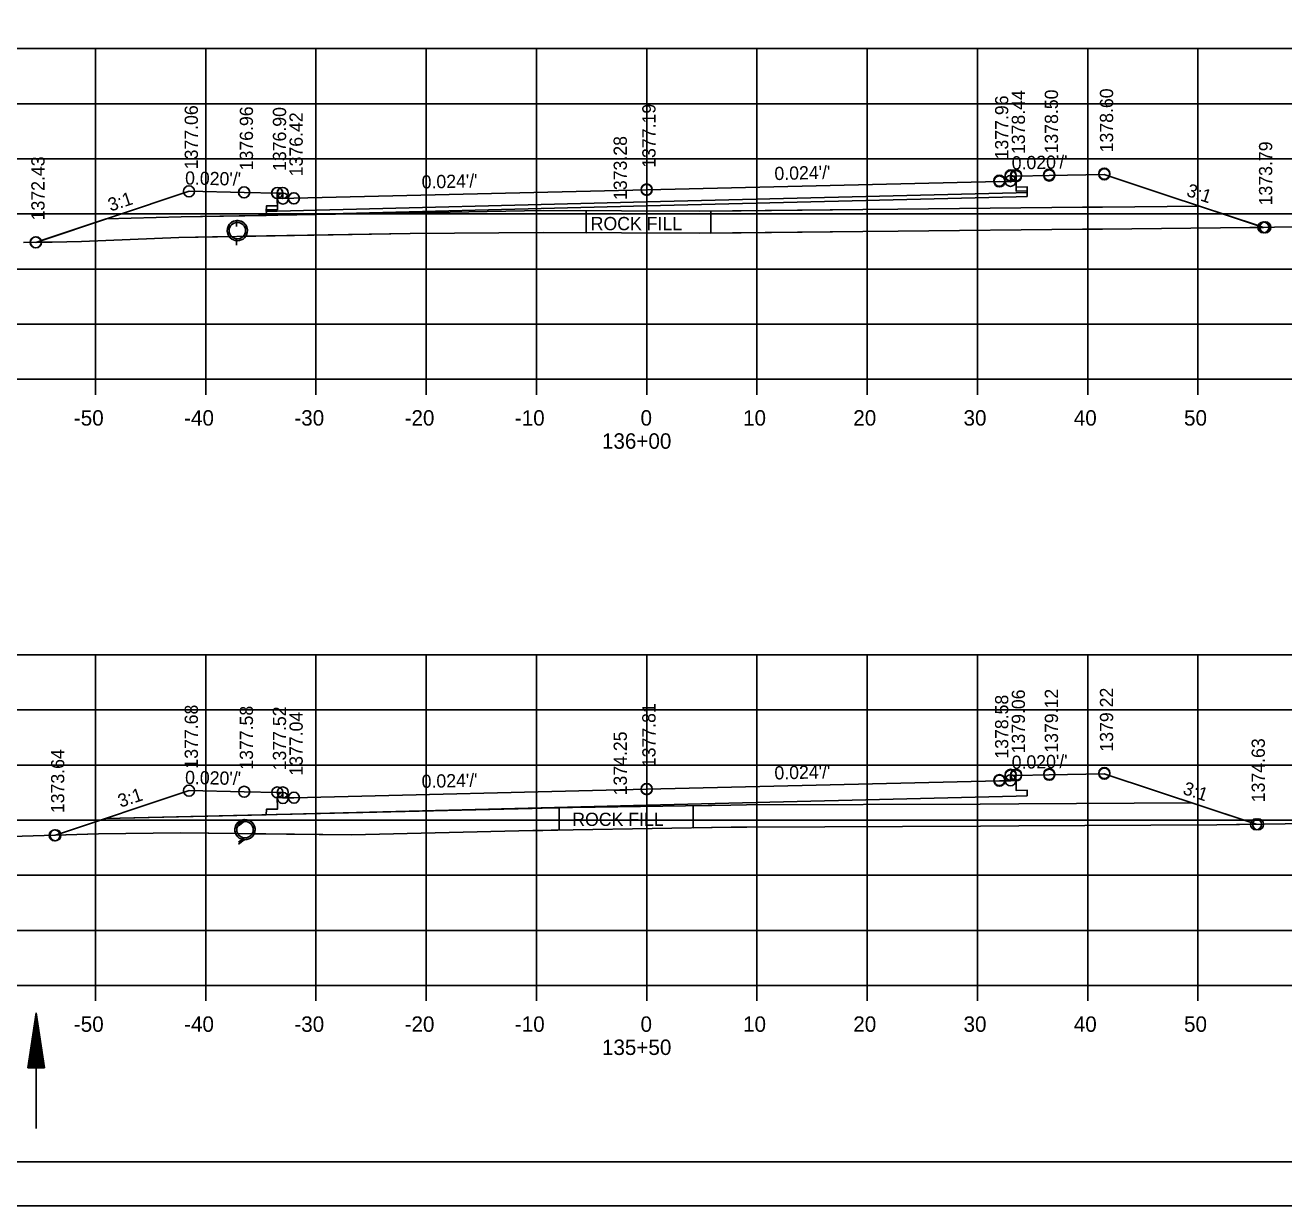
# Model space of a CAD drawing. Extents: x 1374311 to 1383814, y 384102 to 406278.
# Drawn here: x 1381572.3 to 1381686.5, y 388164.7 to 388271.8 of the extents above; entities that cross this region are included whole.
import ezdxf

# ---------------------------------------------------------------- set-up
doc = ezdxf.new("R2010")
doc.units = 0
for name, color, linetype in [('R_Axis', 7, 'Continuous'), ('R_Axis Annot', 7, 'Continuous'), ('R_Border', 7, 'Continuous'), ('R_Draft', 7, 'Continuous'), ('R_Exist Surface', 7, 'Continuous'), ('R_Fin Surface', 7, 'Continuous'), ('R_Grid', 7, 'Continuous'), ('R_No Plot', 7, 'Continuous'), ('R_Water', 7, 'Continuous'), ('R_Xsect Elev', 7, 'Continuous'), ('R_Xsect Slope', 7, 'Continuous')]:
    doc.layers.add(name, color=color, linetype=linetype)

msp = doc.modelspace()

# ---------------------------------------------------------------- linework, layer by layer
at = {"layer": 'R_Axis'}
for p, q in [((1381488.66, 388239.67), (1381768.66, 388239.67)), ((1381578.66, 388238.27), (1381578.66, 388239.67)), ((1381588.66, 388238.27), (1381588.66, 388239.67)), ((1381598.66, 388238.27), (1381598.66, 388239.67)), ((1381608.66, 388238.27), (1381608.66, 388239.67)), ((1381618.66, 388238.27), (1381618.66, 388239.67)), ((1381628.66, 388238.27), (1381628.66, 388239.67)), ((1381638.66, 388238.27), (1381638.66, 388239.67)), ((1381648.66, 388238.27), (1381648.66, 388239.67)), ((1381658.66, 388238.27), (1381658.66, 388239.67)), ((1381668.66, 388238.27), (1381668.66, 388239.67)), ((1381678.66, 388238.27), (1381678.66, 388239.67)), ((1381488.66, 388184.67), (1381768.66, 388184.67)), ((1381578.66, 388183.27), (1381578.66, 388184.67)), ((1381588.66, 388183.27), (1381588.66, 388184.67)), ((1381598.66, 388183.27), (1381598.66, 388184.67)), ((1381608.66, 388183.27), (1381608.66, 388184.67)), ((1381618.66, 388183.27), (1381618.66, 388184.67)), ((1381628.66, 388183.27), (1381628.66, 388184.67)), ((1381638.66, 388183.27), (1381638.66, 388184.67)), ((1381648.66, 388183.27), (1381648.66, 388184.67)), ((1381658.66, 388183.27), (1381658.66, 388184.67)), ((1381668.66, 388183.27), (1381668.66, 388184.67)), ((1381678.66, 388183.27), (1381678.66, 388184.67))]:
    msp.add_line(p, q, dxfattribs=at)
at = {"layer": 'R_Border'}
msp.add_line((1381786.84, 388168.67), (1381470.66, 388168.67), dxfattribs=at)
at = {"layer": 'R_Draft'}
for p, q in [((1381572.54, 388177.19), (1381573.29, 388182.19)), ((1381572.67, 388177.19), (1381573.29, 388181.36)), ((1381574.04, 388177.19), (1381573.29, 388182.19)), ((1381573.92, 388177.19), (1381573.29, 388181.36)), ((1381572.79, 388177.19), (1381573.29, 388180.5)), ((1381573.79, 388177.19), (1381573.29, 388180.5)), ((1381572.92, 388177.19), (1381573.29, 388179.67)), ((1381573.66, 388177.19), (1381573.29, 388179.67)), ((1381573.05, 388177.19), (1381573.29, 388178.82)), ((1381573.17, 388177.19), (1381573.29, 388177.98)), ((1381573.53, 388177.19), (1381573.29, 388178.82)), ((1381573.41, 388177.19), (1381573.29, 388177.98)), ((1381574.04, 388177.19), (1381572.54, 388177.19))]:
    msp.add_line(p, q, dxfattribs=at)
at = {"layer": 'R_Exist Surface'}
for p, q in [((1381591.46, 388254.07), (1381591.46, 388253.68)), ((1381591.46, 388252.24), (1381591.46, 388251.85)), ((1381592.15, 388199.72), (1381591.63, 388199.33)), ((1381592.15, 388197.89), (1381591.63, 388197.5))]:
    msp.add_line(p, q, dxfattribs=at)
for points in [[(1381572.13, 388252.07), (1381574.74, 388252.12), (1381577.38, 388252.16), (1381586.23, 388252.54), (1381607.22, 388252.89), (1381619.28, 388252.98), (1381633.47, 388252.93), (1381648.28, 388253.08), (1381651.47, 388253.12), (1381668.2, 388253.29), (1381670.01, 388253.3), (1381683.37, 388253.44), (1381687.83, 388253.5), (1381688.15, 388253.5), (1381708.29, 388253.81), (1381710.19, 388253.82), (1381728.11, 388254.09), (1381731.48, 388254.11), (1381747.31, 388254.33), (1381752.06, 388254.37), (1381757.72, 388254.57), (1381768.66, 388254.74)], [(1381561.13, 388197.89), (1381578.95, 388198.43), (1381586.36, 388198.52), (1381601.87, 388198.35), (1381618.32, 388198.73), (1381618.84, 388198.74), (1381619.23, 388198.75), (1381621.98, 388198.81), (1381636.31, 388199.03), (1381637.73, 388199.05), (1381658.93, 388199.13), (1381662.43, 388199.17), (1381680.38, 388199.25), (1381686.58, 388199.33), (1381702.39, 388199.6), (1381710.92, 388199.71), (1381721.8, 388199.86), (1381733.98, 388200.06), (1381747.51, 388200.24), (1381752.11, 388200.35), (1381756.03, 388200.45), (1381768.66, 388200.86)]]:
    msp.add_lwpolyline(points, dxfattribs=at)
for centre in [(1381591.53, 388253.16), (1381592.22, 388198.81)]:
    msp.add_circle(centre, 0.917, dxfattribs=at)
at = {"layer": 'R_Fin Surface'}
for p, q in [((1381623.17, 388252.97), (1381623.17, 388254.97)), ((1381623.17, 388252.97), (1381623.17, 388254.97)), ((1381634.49, 388252.94), (1381634.49, 388254.94)), ((1381634.49, 388254.94), (1381634.49, 388252.94)), ((1381684.12, 388253.61), (1381678.79, 388255.39)), ((1381579.63, 388254.22), (1381573.73, 388252.26)), ((1381591.46, 388254.07), (1381591.46, 388254.07)), ((1381648.28, 388253.08), (1381651.47, 388253.12)), ((1381651.47, 388253.12), (1381668.2, 388253.29)), ((1381668.2, 388253.29), (1381670.01, 388253.3)), ((1381670.01, 388253.3), (1381683.37, 388253.44)), ((1381683.37, 388253.44), (1381684.1, 388253.45)), ((1381573.76, 388252.1), (1381574.74, 388252.12)), ((1381574.74, 388252.12), (1381577.38, 388252.16)), ((1381592.29, 388252.65), (1381607.22, 388252.89)), ((1381607.22, 388252.89), (1381619.28, 388252.98)), ((1381619.28, 388252.98), (1381623.17, 388252.97)), ((1381634.49, 388252.94), (1381648.28, 388253.08)), ((1381620.73, 388200.79), (1381620.73, 388198.79)), ((1381620.73, 388198.79), (1381620.73, 388200.79)), ((1381632.87, 388200.98), (1381632.87, 388198.98)), ((1381632.87, 388200.98), (1381632.87, 388198.98)), ((1381683.93, 388199.3), (1381678.11, 388201.24)), ((1381579.58, 388199.83), (1381575.03, 388198.31)), ((1381594.15, 388200.17), (1381579.58, 388199.83)), ((1381592.14, 388199.72), (1381592.15, 388199.72)), ((1381632.87, 388198.98), (1381636.31, 388199.03))]:
    msp.add_line(p, q, dxfattribs=at)
for points in [[(1381573.24, 388252.09), (1381587.15, 388256.73), (1381592.15, 388256.63), (1381595.15, 388256.57), (1381595.65, 388256.57), (1381595.66, 388256.07), (1381596.66, 388256.09), (1381628.66, 388256.86), (1381660.66, 388257.62), (1381661.66, 388257.6), (1381661.67, 388258.1), (1381662.17, 388258.1), (1381665.17, 388258.16), (1381670.17, 388258.26), (1381684.6, 388253.45)], [(1381662.17, 388257.81), (1381662.18, 388256.73), (1381663.18, 388256.77), (1381663.17, 388256.27), (1381662.17, 388256.24), (1381628.66, 388255.4), (1381595.15, 388254.57), (1381594.15, 388254.54), (1381594.16, 388255.04), (1381595.16, 388255.05), (1381595.15, 388256.21)], [(1381579.63, 388254.22), (1381586.42, 388254.41), (1381607.45, 388254.76), (1381619.28, 388254.98), (1381633.47, 388254.93), (1381648.26, 388255.08), (1381651.44, 388255.12), (1381668.19, 388255.29), (1381670, 388255.3), (1381678.79, 388255.39)], [(1381623.17, 388254.97), (1381619.28, 388254.98), (1381607.45, 388254.76), (1381595.15, 388254.56), (1381594.15, 388254.54), (1381586.42, 388254.41), (1381579.63, 388254.22)], [(1381678.79, 388255.39), (1381670, 388255.3), (1381668.19, 388255.29), (1381651.44, 388255.12), (1381648.26, 388255.08), (1381634.49, 388254.94)], [(1381579.63, 388254.22), (1381579.63, 388254.22)], [(1381591.46, 388254.07), (1381591.46, 388254.07)], [(1381577.38, 388252.16), (1381586.23, 388252.54), (1381590.78, 388252.62)], [(1381575.03, 388198.31), (1381587.15, 388202.35), (1381592.15, 388202.25), (1381595.15, 388202.19), (1381595.65, 388202.19), (1381595.66, 388201.69), (1381596.66, 388201.71), (1381628.66, 388202.48), (1381660.66, 388203.25), (1381661.66, 388203.23), (1381661.67, 388203.73), (1381662.17, 388203.73), (1381665.17, 388203.79), (1381670.17, 388203.89), (1381683.93, 388199.3)], [(1381662.17, 388203.43), (1381662.18, 388202.35), (1381663.18, 388202.39), (1381663.17, 388201.89), (1381662.17, 388201.86), (1381628.66, 388201.03), (1381595.15, 388200.19), (1381594.15, 388200.16), (1381594.16, 388200.66), (1381595.16, 388200.67), (1381595.15, 388201.83)], [(1381579.58, 388199.83), (1381618.28, 388200.73), (1381619.19, 388200.75), (1381621.94, 388200.81), (1381636.28, 388201.03), (1381637.71, 388201.05), (1381658.92, 388201.13), (1381662.42, 388201.17), (1381678.11, 388201.24)], [(1381620.73, 388200.79), (1381619.19, 388200.75), (1381618.28, 388200.73), (1381596.51, 388200.22)], [(1381678.11, 388201.24), (1381662.42, 388201.17), (1381658.92, 388201.13), (1381637.71, 388201.05), (1381636.28, 388201.03), (1381632.87, 388200.98)], [(1381592.15, 388199.72), (1381592.15, 388199.72)], [(1381596.51, 388200.22), (1381595.15, 388200.19), (1381594.15, 388200.16)], [(1381594.15, 388200.16), (1381594.15, 388200.17)], [(1381575.03, 388198.31), (1381578.95, 388198.43), (1381586.36, 388198.52), (1381591.37, 388198.46)], [(1381593.06, 388198.44), (1381601.87, 388198.35), (1381618.32, 388198.73), (1381618.84, 388198.74), (1381619.23, 388198.75), (1381620.73, 388198.79)], [(1381620.73, 388198.79), (1381620.73, 388198.79)], [(1381636.31, 388199.03), (1381637.73, 388199.05), (1381658.93, 388199.13), (1381662.43, 388199.17), (1381680.38, 388199.25), (1381683.93, 388199.3)], [(1381683.93, 388199.3), (1381683.93, 388199.3)], [(1381575.03, 388198.31), (1381575.03, 388198.31)]]:
    msp.add_lwpolyline(points, dxfattribs=at)
for centre, radius, start, end in [((1381591.53, 388253.16), 0.917, 94.3218, 215.6764), ((1381591.53, 388253.16), 0.917, 326.2354, 94.3096), ((1381684.6, 388253.45), 0.5, 161.5651, 180.7702), ((1381573.26, 388252.1), 0.5, 0.1362, 18.2039), ((1381592.22, 388198.81), 0.917, 94.5632, 202.0149), ((1381592.22, 388198.81), 0.917, 336.7174, 94.3096)]:
    msp.add_arc(centre, radius, start, end, dxfattribs=at)
at = {"layer": 'R_Grid'}
for p, q in [((1381488.66, 388269.67), (1381768.66, 388269.67)), ((1381578.66, 388239.67), (1381578.66, 388269.67)), ((1381588.66, 388239.67), (1381588.66, 388269.67)), ((1381598.66, 388239.67), (1381598.66, 388269.67)), ((1381608.66, 388239.67), (1381608.66, 388269.67)), ((1381618.66, 388239.67), (1381618.66, 388269.67)), ((1381628.66, 388239.67), (1381628.66, 388269.67)), ((1381638.66, 388239.67), (1381638.66, 388269.67)), ((1381648.66, 388239.67), (1381648.66, 388269.67)), ((1381658.66, 388239.67), (1381658.66, 388269.67)), ((1381668.66, 388239.67), (1381668.66, 388269.67)), ((1381678.66, 388239.67), (1381678.66, 388269.67)), ((1381488.66, 388264.67), (1381768.66, 388264.67)), ((1381488.66, 388259.67), (1381768.66, 388259.67)), ((1381488.66, 388254.67), (1381768.66, 388254.67)), ((1381488.66, 388249.67), (1381768.66, 388249.67)), ((1381488.66, 388244.67), (1381768.66, 388244.67)), ((1381488.66, 388239.67), (1381768.66, 388239.67)), ((1381488.66, 388214.67), (1381768.66, 388214.67)), ((1381578.66, 388184.67), (1381578.66, 388214.67)), ((1381588.66, 388184.67), (1381588.66, 388214.67)), ((1381598.66, 388184.67), (1381598.66, 388214.67)), ((1381608.66, 388184.67), (1381608.66, 388214.67)), ((1381618.66, 388184.67), (1381618.66, 388214.67)), ((1381628.66, 388184.67), (1381628.66, 388214.67)), ((1381638.66, 388184.67), (1381638.66, 388214.67)), ((1381648.66, 388184.67), (1381648.66, 388214.67)), ((1381658.66, 388184.67), (1381658.66, 388214.67)), ((1381668.66, 388184.67), (1381668.66, 388214.67)), ((1381678.66, 388184.67), (1381678.66, 388214.67)), ((1381488.66, 388209.67), (1381768.66, 388209.67)), ((1381488.66, 388204.67), (1381768.66, 388204.67)), ((1381488.66, 388199.67), (1381768.66, 388199.67)), ((1381488.66, 388194.67), (1381768.66, 388194.67)), ((1381488.66, 388189.67), (1381768.66, 388189.67)), ((1381488.66, 388184.67), (1381768.66, 388184.67))]:
    msp.add_line(p, q, dxfattribs=at)
at = {"layer": 'R_No Plot'}
msp.add_line((1381458.26, 388164.69), (1381791.59, 388164.69), dxfattribs=at)
for points in [[(1381458.25, 388378.02), (1381791.59, 388378.02), (1381791.59, 388164.68), (1381458.25, 388164.68)], [(1381704.58, 388374.13), (1381704.58, 388364.25), (1381740.31, 388364.25), (1381740.31, 388361.33), (1381763.51, 388361.33), (1381763.51, 388338.11), (1381786.84, 388338.11), (1381786.84, 388168.67), (1381470.66, 388168.67), (1381470.66, 388374.13)], [(1381573.24, 388252.09), (1381574.74, 388252.12), (1381577.38, 388252.16), (1381586.23, 388252.54), (1381607.22, 388252.89), (1381619.28, 388252.98), (1381633.47, 388252.93), (1381648.28, 388253.08), (1381651.47, 388253.12), (1381668.2, 388253.29), (1381670.01, 388253.3), (1381683.37, 388253.44), (1381684.6, 388253.45), (1381670.17, 388258.26), (1381665.17, 388258.16), (1381662.17, 388258.1), (1381662.18, 388257.09), (1381663.18, 388257.13), (1381663.17, 388256.63), (1381662.17, 388256.6), (1381628.66, 388255.76), (1381595.15, 388254.93), (1381594.15, 388254.9), (1381594.16, 388255.4), (1381595.16, 388255.41), (1381595.15, 388256.57), (1381592.15, 388256.63), (1381587.15, 388256.73)]]:
    msp.add_lwpolyline(points, close=True, dxfattribs=at)
for centre in [(1381670.16, 388258.33), (1381670.17, 388258.33), (1381660.65, 388257.69), (1381660.66, 388257.69), (1381660.66, 388257.62), (1381661.66, 388257.67), (1381661.67, 388258.17), (1381661.67, 388258.1), (1381662.16, 388258.17), (1381662.17, 388258.17), (1381662.17, 388258.1), (1381665.16, 388258.23), (1381665.17, 388258.23), (1381665.17, 388258.16), (1381670.17, 388258.26), (1381587.14, 388256.73), (1381587.15, 388256.73), (1381587.15, 388256.73), (1381592.14, 388256.63), (1381592.15, 388256.63), (1381592.15, 388256.63), (1381595.14, 388256.57), (1381595.15, 388256.57), (1381595.15, 388256.57), (1381595.64, 388256.57), (1381595.65, 388256.57), (1381595.65, 388256.57), (1381595.66, 388256.07), (1381596.65, 388256.09), (1381596.66, 388256.09), (1381596.66, 388256.09), (1381628.65, 388256.89), (1381628.66, 388256.89), (1381628.66, 388256.86), (1381684.6, 388253.45), (1381684.73, 388253.47), (1381684.78, 388253.46), (1381573.24, 388252.09), (1381573.24, 388252.09), (1381573.24, 388252.09), (1381573.24, 388252.09), (1381573.26, 388252.1), (1381573.26, 388252.1), (1381661.67, 388203.79), (1381661.67, 388203.79), (1381661.67, 388203.73), (1381662.17, 388203.79), (1381662.17, 388203.79), (1381662.17, 388203.73), (1381665.17, 388203.85), (1381665.17, 388203.85), (1381665.17, 388203.79), (1381670.17, 388203.95), (1381670.17, 388203.95), (1381670.17, 388203.89), (1381628.66, 388202.51), (1381628.66, 388202.51), (1381628.66, 388202.48), (1381660.66, 388203.31), (1381660.66, 388203.31), (1381660.66, 388203.25), (1381661.66, 388203.29), (1381587.15, 388202.35), (1381587.15, 388202.35), (1381587.15, 388202.35), (1381592.15, 388202.25), (1381592.15, 388202.25), (1381592.15, 388202.25), (1381595.15, 388202.19), (1381595.15, 388202.19), (1381595.15, 388202.19), (1381595.65, 388202.19), (1381595.65, 388202.19), (1381595.65, 388202.19), (1381595.66, 388201.69), (1381596.66, 388201.71), (1381596.66, 388201.71), (1381596.66, 388201.71), (1381683.93, 388199.3), (1381684.12, 388199.3), (1381684.12, 388199.3), (1381574.95, 388198.29), (1381574.95, 388198.29), (1381575.02, 388198.31), (1381575.02, 388198.31), (1381575.03, 388198.31), (1381575.03, 388198.31)]:
    msp.add_circle(centre, 0.5, dxfattribs=at)
at = {"layer": 'R_Water'}
for p, q in [((1381591.46, 388253.91), (1381591.46, 388253.52)), ((1381591.46, 388252.41), (1381591.46, 388252.02)), ((1381592.15, 388199.56), (1381591.63, 388199.17)), ((1381592.15, 388198.06), (1381591.63, 388197.67)), ((1381573.29, 388171.69), (1381573.29, 388182.19))]:
    msp.add_line(p, q, dxfattribs=at)
for centre in [(1381591.53, 388253.16), (1381592.22, 388198.81)]:
    msp.add_circle(centre, 0.75, dxfattribs=at)

# ---------------------------------------------------------------- texts
at = {"layer": 'R_Axis Annot'}
for s, p in [('-50', (1381576.7, 388235.47)), ('-40', (1381586.7, 388235.47)), ('-30', (1381596.7, 388235.47)), ('-20', (1381606.7, 388235.47)), ('-10', (1381616.7, 388235.47)), ('0', (1381628.1, 388235.47)), ('10', (1381637.4, 388235.47)), ('20', (1381647.4, 388235.47)), ('30', (1381657.4, 388235.47)), ('40', (1381667.4, 388235.47)), ('50', (1381677.4, 388235.47)), ('136+00', (1381624.6, 388233.37)), ('-50', (1381576.7, 388180.47)), ('-40', (1381586.7, 388180.47)), ('-30', (1381596.7, 388180.47)), ('-20', (1381606.7, 388180.47)), ('-10', (1381616.7, 388180.47)), ('0', (1381628.1, 388180.47)), ('10', (1381637.4, 388180.47)), ('20', (1381647.4, 388180.47)), ('30', (1381657.4, 388180.47)), ('40', (1381667.4, 388180.47)), ('50', (1381677.4, 388180.47)), ('135+50', (1381624.6, 388178.37))]:
    msp.add_text(s, height=1.4, dxfattribs=at).set_placement(p)
at = {"layer": 'R_Fin Surface'}
for p in [(1381623.58, 388253.2), (1381621.91, 388199.15)]:
    msp.add_text('ROCK FILL', height=1.2, dxfattribs=at).set_placement(p)
at = {"layer": 'R_Xsect Elev'}
for s, p in [('1378.44', (1381662.97, 388260.1)), ('1378.50', (1381665.97, 388260.16)), ('1378.60', (1381670.97, 388260.26)), ('1377.19', (1381629.46, 388258.86)), ('1377.96', (1381661.46, 388259.62)), ('1377.06', (1381587.95, 388258.73)), ('1376.96', (1381592.95, 388258.63)), ('1376.90', (1381595.95, 388258.57)), ('1376.42', (1381597.46, 388258.09)), ('1373.28', (1381626.86, 388255.94)), ('1373.79', (1381685.4, 388255.45)), ('1372.43', (1381574.04, 388254.09)), ('1378.58', (1381661.46, 388205.25)), ('1379.06', (1381662.97, 388205.73)), ('1379.12', (1381665.97, 388205.79)), ('1379.22', (1381670.97, 388205.89)), ('1377.68', (1381587.95, 388204.35)), ('1377.58', (1381592.95, 388204.25)), ('1377.52', (1381595.95, 388204.19)), ('1377.81', (1381629.46, 388204.48)), ('1377.04', (1381597.46, 388203.71)), ('1374.25', (1381626.86, 388201.92)), ('1374.63', (1381684.73, 388201.3)), ('1373.64', (1381575.83, 388200.31))]:
    msp.add_text(s, height=1.2, rotation=90, dxfattribs=at).set_placement(p)
at = {"layer": 'R_Xsect Slope'}
for s, rotation, p in [("0.020'/'", 1.1458, (1381661.78, 388258.7)), ("0.024'/'", 1.3748, (1381640.26, 388257.74)), ("0.020'/'", 358.8542, (1381586.78, 388257.34)), ("0.024'/'", 1.3748, (1381608.26, 388256.97)), ('3:1', 18.4349, (1381580.03, 388254.88)), ('3:1', 341.5651, (1381677.54, 388256.33)), ("0.020'/'", 1.1458, (1381661.78, 388204.32)), ("0.020'/'", 358.8542, (1381586.78, 388202.96)), ("0.024'/'", 1.3748, (1381640.26, 388203.36)), ("0.024'/'", 1.3748, (1381608.26, 388202.59)), ('3:1', 341.5651, (1381677.21, 388202.07)), ('3:1', 18.4349, (1381580.93, 388200.8))]:
    msp.add_text(s, height=1.2, rotation=rotation, dxfattribs=at).set_placement(p)

doc.saveas('drawing.dxf')
